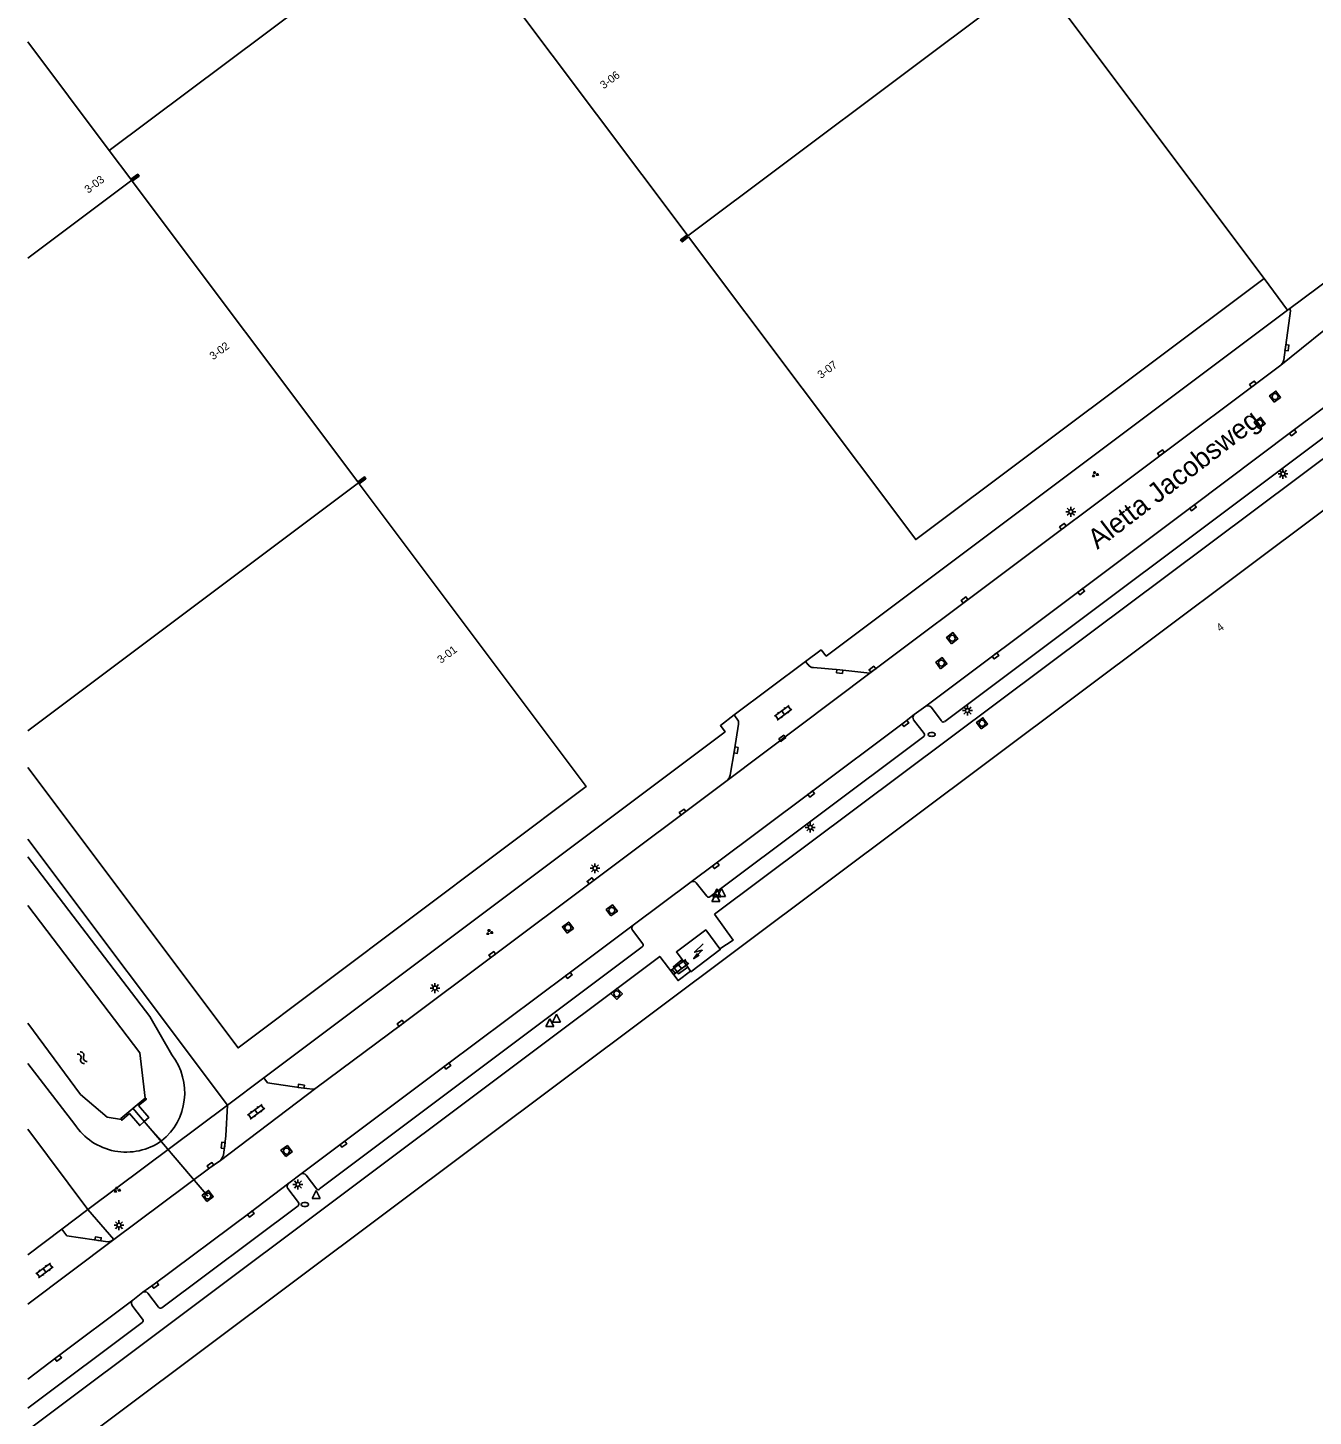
# Model space of a CAD drawing. Extents: x 131000 to 133013, y 393000 to 396501.
# Drawn here: x 131000 to 131162.3, y 393995.3 to 394170.7 of the extents above; entities that cross this region are included whole.
import ezdxf

# ---------------------------------------------------------------- set-up
doc = ezdxf.new("R2010")
doc.units = 0
for name, color, linetype in [('gg-afsc-hekwerk', 7, 'Continuous'), ('gg-anno-huisnummerreeks BGT', 7, 'Continuous'), ('gg-anno-openbare ruimte label', 7, 'Continuous'), ('gg-bbg-bijgebouw', 7, 'Continuous'), ('gg-bbg-hoofdgebouw', 7, 'Continuous'), ('gg-bbg-tussenscheiding', 7, 'Continuous'), ('gg-knt-verharding', 7, 'Continuous'), ('gg-kntw-bovenkant insteek waterloop', 7, 'Continuous'), ('gg-kntw-waterlijn', 7, 'Continuous'), ('gg-kwrk-duiker nz buis', 7, 'Continuous'), ('gg-kwrk-uitstroombak niveau min 01', 7, 'Continuous'), ('gt-grn-groengrens', 7, 'Continuous'), ('gt-symb-brandkraan', 7, 'Continuous'), ('gt-symb-groenvak', 7, 'Continuous'), ('gt-symb-klinker verharding', 7, 'Continuous'), ('gt-symb-kolk', 7, 'Continuous'), ('gt-symb-lichtmast', 7, 'Continuous'), ('gt-symb-rioolschacht', 7, 'Continuous'), ('gt-symb-trafo symbool', 7, 'Continuous'), ('gt-symb-waterafsluiter', 7, 'Continuous'), ('gt-symb-watersymbool', 7, 'Continuous')]:
    doc.layers.add(name, color=color, linetype=linetype)

# ---------------------------------------------------------------- blocks, each defined once
blk = doc.blocks.new('gt0-KOLK')
at = {"layer": 'gt-symb-kolk'}
blk.add_lwpolyline([(0, 0), (0.37, 0), (0.37, 0.4), (-0.38, 0.4), (-0.38, 0), (0, 0)], dxfattribs=at)
blk = doc.blocks.new('gt0-KL1')
at = {"layer": 'gt-symb-klinker verharding'}
for p, q in [((-1.15, 0.3), (1.15, 0.3)), ((-1, -0.3), (-1, 0.3)), ((-0.5, 0.3), (-0.5, 0.45)), ((0, -0.3), (0, 0.3)), ((0.5, 0.3), (0.5, 0.45)), ((1, -0.3), (1, 0.3)), ((-1.15, -0.3), (1.15, -0.3)), ((-0.5, -0.45), (-0.5, -0.3)), ((0.5, -0.45), (0.5, -0.3))]:
    blk.add_line(p, q, dxfattribs=at)
blk = doc.blocks.new('gt0-LMAST')
at = {"layer": 'gt-symb-lichtmast'}
for p, q in [((-0.18, 0.17), (-0.45, 0.44)), ((-0.01, 0.25), (-0.01, 0.62)), ((0.17, 0.17), (0.44, 0.44)), ((-0.26, 0), (-0.63, 0)), ((-0.18, -0.18), (-0.45, -0.45)), ((-0.01, -0.25), (-0.01, -0.63)), ((0.44, -0.45), (0.17, -0.18)), ((0.24, 0), (0.62, 0))]:
    blk.add_line(p, q, dxfattribs=at)
blk.add_circle((-0.01, 0), 0.25, dxfattribs=at)
blk = doc.blocks.new('gt0-RS')
at = {"layer": 'gt-symb-rioolschacht'}
blk.add_lwpolyline([(-0.5, -0.5), (0.5, -0.5), (0.5, 0.5), (-0.5, 0.5)], close=True, dxfattribs=at)
blk.add_circle((0, 0), 0.375, dxfattribs=at)
blk = doc.blocks.new('gt0-GRVAK')
at = {"layer": 'gt-symb-groenvak'}
for p, q in [((-0.11, 0.19), (-0.23, 0.24)), ((-0.18, 0.15), (0.09, 0.15)), ((-0.09, 0.21), (-0.16, 0.32)), ((-0.05, 0.21), (-0.05, 0.39)), ((0, 0.21), (0.06, 0.32)), ((0.02, 0.19), (0.13, 0.24)), ((0.26, -0.05), (0.2, 0.06)), ((0.31, -0.05), (0.31, 0.13)), ((0.35, -0.05), (0.41, 0.06)), ((-0.24, -0.23), (-0.36, -0.18)), ((-0.32, -0.26), (-0.05, -0.26)), ((-0.23, -0.21), (-0.29, -0.09)), ((-0.18, -0.2), (-0.18, -0.02)), ((-0.14, -0.21), (-0.07, -0.09)), ((-0.12, -0.23), (0, -0.18)), ((0.24, -0.07), (0.12, -0.02)), ((0.17, -0.11), (0.44, -0.11)), ((0.37, -0.07), (0.49, -0.02))]:
    blk.add_line(p, q, dxfattribs=at)
blk = doc.blocks.new('gt0-HSP')
at = {"layer": 'gt-symb-trafo symbool'}
for points in [[(0.77, 0.75), (-0.53, 0), (0.47, 0), (-0.83, -0.75)], [(-0.22, -0.24), (-0.83, -0.75), (-0.08, -0.48)]]:
    blk.add_lwpolyline(points, dxfattribs=at)
blk = doc.blocks.new('gt0-WAFSL')
at = {"layer": 'gt-symb-waterafsluiter'}
for p, q in [((-0.5, -0.33), (0, 0.67)), ((0, 0.67), (0.5, -0.33)), ((0.5, -0.33), (-0.5, -0.33))]:
    blk.add_line(p, q, dxfattribs=at)
blk = doc.blocks.new('gt0-BR')
at = {"layer": 'gt-symb-brandkraan'}
for centre, radius, start, end in [((-0.24, 0), 0.206, 107.5669, 252.4331), ((0.6, -2.66), 3, 106.892, 107.5669), ((0, -0.69), 0.938, 73.108, 106.892), ((-0.6, -2.66), 3, 72.4331, 73.108), ((0.24, 0), 0.206, 287.567, 72.4331), ((0.6, 2.66), 3, 252.4331, 253.108), ((0, 0.69), 0.938, 253.108, 286.8921), ((-0.6, 2.66), 3, 286.8921, 287.567)]:
    blk.add_arc(centre, radius, start, end, dxfattribs=at)
blk = doc.blocks.new('gt0-WA')
at = {"layer": 'gt-symb-watersymbool'}
for centre, start, end in [((-0.32, 0.02), 28.0725, 151.9275), ((0.43, 0.42), 208.0725, 331.9275), ((-0.32, -0.43), 28.0725, 151.9275), ((0.43, -0.03), 208.0725, 331.9275)]:
    blk.add_arc(centre, 0.425, start, end, dxfattribs=at)

msp = doc.modelspace()

# ---------------------------------------------------------------- linework, layer by layer
at = {"layer": 'gg-afsc-hekwerk'}
for p, q in [((131219.56, 394158.16), (131143.73, 394101.43)), ((131159.39, 394135.27), (131167.44, 394141.3)), ((131156.14, 394139.07), (131159.11, 394135.06)), ((131159.11, 394135.06), (131159.39, 394135.27)), ((131143.73, 394101.43), (131134.37, 394094.43)), ((131134.37, 394094.43), (131086.71, 394058.78)), ((131000, 394068.24), (131025.21, 394034.62)), ((131029.81, 394038.1), (131025.21, 394034.62)), ((131000, 394031.62), (131007.6, 394021.47)), ((131004.3, 394018.98), (131007.6, 394021.47)), ((131000, 394015.75), (131004.3, 394018.98))]:
    msp.add_line(p, q, dxfattribs=at)
for points in [[(131159.11, 394135.06), (131100.84, 394091.37), (131100.2, 394092.14), (131098.23, 394090.69)], [(131089.22, 394083.95), (131087.48, 394082.6), (131088.06, 394081.82), (131029.81, 394038.1)], [(131086.71, 394058.78), (131089.08, 394055.47), (131087.4, 394054.38)], [(131000, 393993.58), (131079.81, 394053.43), (131082.14, 394050.37), (131083.72, 394051.55)]]:
    msp.add_lwpolyline(points, dxfattribs=at)
at = {"layer": 'gg-bbg-bijgebouw'}
for p, q in [((131082.64, 394053.02), (131083.35, 394052.06)), ((131083.35, 394052.06), (131083.72, 394051.55))]:
    msp.add_line(p, q, dxfattribs=at)
for points in [[(131087.4, 394054.38), (131085.62, 394056.77), (131081.92, 394054), (131082.64, 394053.02)], [(131083.72, 394051.55), (131083.76, 394051.5), (131087.46, 394054.3), (131087.4, 394054.38)]]:
    msp.add_lwpolyline(points, dxfattribs=at)
at = {"layer": 'gg-bbg-hoofdgebouw'}
msp.add_line((131127.37, 394177.45), (131156.14, 394139.07), dxfattribs=at)
for points in [[(131010.29, 394155.23), (131044.99, 394181.25), (131045.38, 394180.73), (131048.51, 394183.08), (131048.12, 394183.6), (131051.89, 394186.43)], [(131082.54, 394143.82), (131082.45, 394143.95), (131083.28, 394144.57), (131054.78, 394182.57), (131053.95, 394181.95), (131053.86, 394182.07)], [(131010.29, 394155.23), (131013.01, 394151.6), (131013.88, 394152.24), (131013.97, 394152.12)], [(131042.61, 394113.9), (131042.52, 394114.03), (131041.67, 394113.39), (131013.2, 394151.35), (131014.06, 394152), (131013.97, 394152.12)], [(131082.54, 394143.82), (131082.63, 394143.7), (131083.46, 394144.32)], [(131156.14, 394139.07), (131112.14, 394106.08), (131083.46, 394144.32)], [(131000, 393987.17), (131090.25, 394054.81), (131206.15, 394141.65), (131265.66, 394062.22), (131265.74, 394062.28), (131275.59, 394049.06), (131159.58, 393962.29), (131087.03, 393907.86), (131077.14, 393921.03), (131077, 393920.93), (131073.7, 393925.33), (131000, 393870.15)], [(131042.61, 394113.9), (131042.71, 394113.78), (131041.86, 394113.14), (131070.54, 394074.9), (131026.56, 394041.88), (131000, 394077.29)]]:
    msp.add_lwpolyline(points, dxfattribs=at)
at = {"layer": 'gg-bbg-tussenscheiding'}
for p, q in [((131082.54, 394143.82), (131127.37, 394177.45)), ((131000, 394168.95), (131010.29, 394155.23)), ((131000, 394141.64), (131013.97, 394152.12)), ((131000, 394081.94), (131042.61, 394113.9))]:
    msp.add_line(p, q, dxfattribs=at)
at = {"layer": 'gg-knt-verharding'}
for p, q in [((131172.89, 394139.91), (131158.25, 394128.13)), ((131106.33, 394089.21), (131158.25, 394128.13)), ((131171.97, 394125.25), (131115.8, 394083.11)), ((131088.35, 394075.64), (131106.33, 394089.21)), ((131089.22, 394083.95), (131098.23, 394090.69)), ((131098.23, 394090.69), (131098.57, 394090.28)), ((131113.42, 394085.05), (131111.96, 394083.98)), ((131115.39, 394083.17), (131114.09, 394084.92)), ((131111.88, 394083.33), (131113.21, 394081.58)), ((131113.16, 394081.19), (131086.16, 394060.97)), ((131083.79, 394062.86), (131076.45, 394057.37)), ((131085.75, 394061.02), (131084.43, 394062.72)), ((131076.37, 394056.74), (131077.67, 394055)), ((131077.61, 394054.64), (131036.86, 394024.05)), ((131024.33, 394027.66), (131036.39, 394036.78)), ((131034.53, 394025.95), (131032.95, 394024.77)), ((131036.52, 394024.03), (131035.18, 394025.8)), ((131032.85, 394024.09), (131034.18, 394022.33)), ((131034.15, 394021.92), (131016.93, 394009.04)), ((131000, 394009.48), (131010.87, 394017.66)), ((131014.54, 394011.01), (131013.26, 394010.02)), ((131016.53, 394009.12), (131015.18, 394010.88)), ((131013.16, 394009.39), (131014.51, 394007.59)), ((131000, 393996.37), (131014.44, 394007.19))]:
    msp.add_line(p, q, dxfattribs=at)
for points in [[(131159.39, 394135.27), (131159.47, 394135), (131158.62, 394128.79), (131158.51, 394128.42), (131158.25, 394128.13)], [(131170.81, 394128.08), (131159.66, 394119.73), (131147.04, 394110.26), (131132.92, 394099.66), (131113.42, 394085.05)], [(131099.22, 394089.92), (131102.55, 394089.62), (131106.33, 394089.21)], [(131111.96, 394083.98), (131110.72, 394083.01), (131098.82, 394074.11), (131086.77, 394065.07), (131083.79, 394062.86)], [(131088.35, 394075.64), (131088.59, 394075.95), (131088.71, 394076.32), (131089.26, 394079.51), (131089.77, 394082.77), (131089.76, 394083.15), (131089.22, 394083.95)], [(131036.39, 394036.78), (131047.21, 394044.82), (131071.19, 394062.82), (131088.35, 394075.64)], [(131076.45, 394057.37), (131068.21, 394051.19), (131052.87, 394039.74), (131034.53, 394025.95)], [(131083.35, 394052.06), (131082.18, 394051.24), (131081.55, 394052.13), (131082.64, 394053.02)], [(131029.81, 394038.1), (131030.29, 394037.46), (131034.51, 394036.82), (131035.97, 394036.67), (131036.19, 394036.68), (131036.39, 394036.78)], [(131025.21, 394034.62), (131025.03, 394030.78), (131024.73, 394028.33), (131024.57, 394027.97), (131024.33, 394027.66)], [(131024.33, 394027.66), (131023.18, 394026.85), (131010.87, 394017.66)], [(131032.95, 394024.77), (131028.05, 394021.05), (131015.98, 394012.04), (131014.54, 394011.01)], [(131010.87, 394017.66), (131010.51, 394017.46), (131010.11, 394017.38), (131004.94, 394018.13), (131004.3, 394018.98)], [(131000, 394000.04), (131003.72, 394002.83), (131013.26, 394010.02)]]:
    msp.add_lwpolyline(points, dxfattribs=at)
for centre, radius, start, end in [((131099.18, 394090.63), 0.706, 209.0618, 272.7842), ((131112.3, 394083.61), 0.505, 132.5891, 213.7876), ((131113.66, 394084.5), 0.595, 44.5091, 114.3549), ((131115.61, 394083.29), 0.255, 209.6331, 315.1032), ((131112.97, 394081.41), 0.293, 311.7602, 35.6241), ((131084.02, 394062.36), 0.55, 41.2778, 114.1778), ((131085.98, 394061.21), 0.299, 219.475, 307.5402), ((131076.83, 394057), 0.531, 135.8162, 210.0224), ((131077.46, 394054.85), 0.257, 305.6948, 37.1205), ((131033.3, 394024.37), 0.532, 131.3482, 211.7306), ((131034.75, 394025.41), 0.581, 42.6741, 112.7526), ((131036.69, 394024.14), 0.196, 211.6286, 332.4141), ((131033.92, 394022.14), 0.315, 316.209, 36.761), ((131014.79, 394010.61), 0.47, 34.521, 122.7562), ((131013.61, 394009.64), 0.513, 132.2131, 209.4793), ((131016.77, 394009.3), 0.304, 217.097, 300.7264), ((131014.28, 394007.42), 0.283, 304.3913, 36.684)]:
    msp.add_arc(centre, radius, start, end, dxfattribs=at)
at = {"layer": 'gg-kntw-bovenkant insteek waterloop'}
msp.add_line((131000, 394039.9), (131005.93, 394032.2), dxfattribs=at)
msp.add_lwpolyline([(131000, 394066.02), (131015.4, 394045.85), (131018.21, 394040.99)], dxfattribs=at)
for centre, radius, start, end in [((131011.99, 394036.22), 7.83, 308.8135, 37.4635), ((131012.43, 394036.51), 7.8, 213.4976, 304.9967)]:
    msp.add_arc(centre, radius, start, end, dxfattribs=at)
at = {"layer": 'gg-kntw-waterlijn'}
for points in [[(131000, 394059.87), (131014.14, 394041.25), (131014.83, 394035.53)], [(131000, 394044.98), (131006.66, 394035.99), (131010.01, 394033.11), (131011.82, 394032.81)]]:
    msp.add_lwpolyline(points, dxfattribs=at)
at = {"layer": 'gg-kwrk-duiker nz buis'}
msp.add_line((131013.28, 394034.24), (131022.73, 394023.16), dxfattribs=at)
at = {"layer": 'gg-kwrk-uitstroombak niveau min 01'}
for points in [[(131014.83, 394035.53), (131011.74, 394032.94), (131011.82, 394032.81)], [(131014.71, 394032.57), (131015.27, 394033.07), (131013.99, 394034.59), (131014.99, 394035.41), (131014.83, 394035.53)], [(131011.82, 394032.81), (131011.86, 394032.74), (131012.84, 394033.59), (131014.15, 394032.06), (131014.71, 394032.57)]]:
    msp.add_lwpolyline(points, dxfattribs=at)
at = {"layer": 'gt-grn-groengrens'}
for p, q in [((131007.6, 394021.47), (131025.21, 394034.62)), ((131014.71, 394032.57), (131016.9, 394030.12)), ((131010.87, 394017.66), (131007.6, 394021.47))]:
    msp.add_line(p, q, dxfattribs=at)

# ---------------------------------------------------------------- block references
at = {"layer": 'gt-symb-brandkraan'}
for p in [(131114.17, 394081.47), (131034.99, 394022.09)]:
    msp.add_blockref('gt0-BR', p, dxfattribs=at)
at = {"layer": 'gt-symb-groenvak'}
for p in [(131134.78, 394114.33), (131058.29, 394056.49), (131011.26, 394023.93)]:
    msp.add_blockref('gt0-GRVAK', p, dxfattribs=at)
at = {"layer": 'gt-symb-klinker verharding'}
for p, rotation in [((131095.4, 394084.21), 36.58342113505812), ((131082.37, 394052.13), 36.583421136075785), ((131028.84, 394033.81), 36.58342113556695), ((131002.11, 394013.77), 36.5834211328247)]:
    msp.add_blockref('gt0-KL1', p, dxfattribs=dict(at, rotation=rotation))
at = {"layer": 'gt-symb-kolk'}
for p, rotation in [((131158.83, 394130.34), -97.99231392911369), ((131154.85, 394125.57), 36.7896996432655), ((131159.66, 394119.73), -143.13010235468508), ((131143.24, 394116.89), 36.789699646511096), ((131147.04, 394110.26), -143.089753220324), ((131130.85, 394107.59), 36.7896996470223), ((131132.92, 394099.66), -143.15915455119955), ((131118.43, 394098.3), 36.789699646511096), ((131122.1, 394091.55), -143.15915455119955), ((131102.55, 394089.62), 174.26090149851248), ((131106.79, 394089.55), 36.95012772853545), ((131110.72, 394083.01), -143.21080058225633), ((131095.41, 394080.82), 36.743796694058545), ((131089.26, 394079.51), -99.32106070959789), ((131098.82, 394074.11), -143.11880427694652), ((131082.83, 394071.51), 36.74379669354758), ((131086.77, 394065.07), -143.47546735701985), ((131071.19, 394062.82), 36.743796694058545), ((131058.79, 394053.5), 36.743796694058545), ((131068.21, 394051.19), -143.2689109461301), ((131047.21, 394044.82), 36.743796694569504), ((131052.87, 394039.74), -143.04940412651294), ((131034.51, 394036.82), -8.219209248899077), ((131024.88, 394029.55), 82.99574075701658), ((131039.74, 394029.86), -143.07200288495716), ((131023.18, 394026.85), 35.311213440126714), ((131028.05, 394021.05), -143.26891094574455), ((131008.86, 394017.55), -8.275892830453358), ((131015.98, 394012.04), -144.2437552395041), ((131003.72, 394002.83), -143.18820837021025)]:
    msp.add_blockref('gt0-KOLK', p, dxfattribs=dict(at, rotation=rotation))
at = {"layer": 'gt-symb-lichtmast'}
for p in [(131158.53, 394114.4), (131131.74, 394109.61), (131118.69, 394084.49), (131098.83, 394069.73), (131071.64, 394064.56), (131051.44, 394049.43), (131034.12, 394024.62), (131011.52, 394019.48)]:
    msp.add_blockref('gt0-LMAST', p, dxfattribs=at)
at = {"layer": 'gt-symb-rioolschacht'}
for p, rotation in [((131157.53, 394124.15), 36.74379669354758), ((131155.59, 394120.82), 36.743796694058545), ((131116.75, 394093.63), 36.743796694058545), ((131115.39, 394090.48), 36.743796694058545), ((131120.53, 394082.88), 36.74379669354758), ((131073.76, 394059.24), 36.74379669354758), ((131068.22, 394057.07), 36.743796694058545), ((131074.39, 394048.71), -45.729326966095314), ((131032.68, 394028.84), 36.743796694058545), ((131022.73, 394023.16), 36.743796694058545)]:
    msp.add_blockref('gt0-RS', p, dxfattribs=dict(at, rotation=rotation))
at = {"layer": 'gt-symb-trafo symbool', "rotation": 14.828108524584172}
msp.add_blockref('gt0-HSP', (131084.73, 394054.09), dxfattribs=at)
at = {"layer": 'gt-symb-waterafsluiter'}
for p in [(131086.89, 394060.68), (131087.02, 394061.29), (131087.63, 394061.33), (131065.93, 394044.89), (131066.76, 394045.46), (131036.42, 394023.17)]:
    msp.add_blockref('gt0-WAFSL', p, dxfattribs=at)
at = {"layer": 'gt-symb-watersymbool', "rotation": -52.63746931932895}
msp.add_blockref('gt0-WA', (131006.85, 394040.68), dxfattribs=at)

# ---------------------------------------------------------------- texts
at = {"layer": 'gg-anno-huisnummerreeks BGT'}
for s, rotation, p in [('3-06', 36.9, (131072.74, 394162.96)), ('3-03', 36.9, (131007.63, 394149.77)), ('3-02', 36.9, (131023.42, 394128.73)), ('3-07', 36.9, (131100.19, 394126.36)), ('4', 36.8, (131150.58, 394094.4)), ('3-01', 36.9, (131052.18, 394090.38))]:
    msp.add_text(s, height=1, rotation=rotation, dxfattribs=at).set_placement(p)
at = {"layer": 'gg-anno-openbare ruimte label'}
msp.add_text('Aletta Jacobsweg', height=2.5, rotation=37.5, dxfattribs=at).set_placement((131135.09, 394104.78))

doc.saveas('drawing.dxf')
